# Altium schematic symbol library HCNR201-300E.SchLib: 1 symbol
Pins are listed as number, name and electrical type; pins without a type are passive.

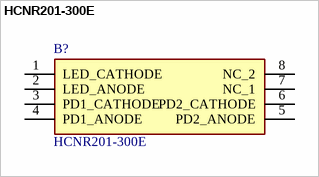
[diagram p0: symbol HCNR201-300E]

## HCNR201-300E
designator B?
Broadcom, HCNR201-300E DC Input Photodiode Output Optocoupler, Surface Mount, 8-Pin PDIP-W; Manufacturer_Name: Avago Technologies; Geometry.Height: 5mm
footprint HCNR201300E
pins: 1 LED_CATHODE, 2 LED_ANODE, 3 PD1_CATHODE, 4 PD1_ANODE, 5 PD2_ANODE, 6 PD2_CATHODE, 7 NC_1, 8 NC_2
